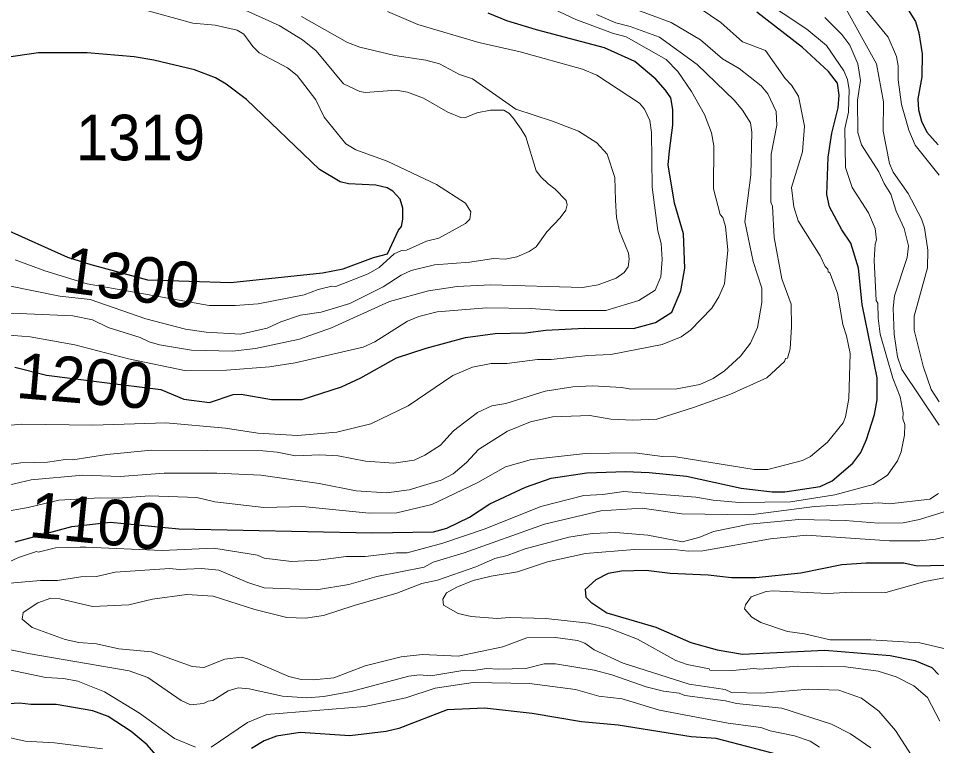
# Model space of a CAD drawing. Extents: x 598.3 to 623.2, y 6902.2 to 6930.1.
# Drawn here: x 611.511 to 613.12, y 6916.884 to 6918.158 of the extents above; entities that cross this region are included whole.
import ezdxf
from ezdxf.enums import TextEntityAlignment as Align

# ---------------------------------------------------------------- set-up
doc = ezdxf.new("R2010")
doc.units = 0
doc.header["$LTSCALE"] = 0.032
doc.layers.add('1', color=7, linetype='Continuous', lineweight=25)
doc.layers.add('2', color=7, linetype='Continuous', lineweight=13)
doc.layers.add('21', color=7, linetype='Continuous')
doc.layers.add('61', color=7, linetype='Continuous')

msp = doc.modelspace()

# ---------------------------------------------------------------- linework, layer by layer
at = {"layer": '1'}
for points in [[(613.057, 6918.194), (613.0824, 6918.1525), (613.0882, 6918.1326), (613.0943, 6918.0959), (613.0936, 6918.0553), (613.0864, 6918.0171), (613.088, 6917.9976), (613.0929, 6917.9779), (613.1024, 6917.9588), (613.1221, 6917.9365)], [(611.5054, 6917.2411), (611.6046, 6917.2681), (611.6723, 6917.2757), (611.7924, 6917.2638), (612.1301, 6917.2567), (612.2383, 6917.2584), (612.2614, 6917.265), (612.3015, 6917.2844), (612.3366, 6917.3076), (612.3996, 6917.3367), (612.4443, 6917.3524), (612.5065, 6917.3619), (612.5745, 6917.3643), (612.6161, 6917.3628), (612.6813, 6917.3563), (612.7772, 6917.335), (612.8315, 6917.3288), (612.8535, 6917.3288), (612.9157, 6917.3383), (612.9363, 6917.348), (612.9728, 6917.3787), (612.9868, 6917.3976), (612.9968, 6917.4202), (613.0109, 6917.464), (613.0152, 6917.4899), (613.0151, 6917.5281), (612.9893, 6917.6571), (612.9827, 6917.7205), (612.969, 6917.7642), (612.9532, 6917.7876), (612.9316, 6917.8276), (612.927, 6917.8497), (612.9294, 6917.9151), (612.9358, 6917.9569), (612.9472, 6918.0014), (612.9487, 6918.0235), (612.9461, 6918.0446), (612.9303, 6918.0651), (612.8843, 6918.1072), (612.8044, 6918.1691)], [(612.6269, 6917.6252), (612.6559, 6917.6432), (612.6713, 6917.6807), (612.6785, 6917.7207), (612.6759, 6917.7804), (612.6605, 6917.8341), (612.6493, 6917.9015), (612.6517, 6917.9259), (612.6573, 6917.9707), (612.6574, 6917.9984), (612.6541, 6918.0189), (612.6444, 6918.0323), (612.6275, 6918.0513), (612.5907, 6918.0825), (612.5378, 6918.1065), (612.4184, 6918.138), (612.3669, 6918.1539), (612.3342, 6918.1671)], [(611.4881, 6917.7889), (611.5972, 6917.7398), (611.638, 6917.7271), (611.7371, 6917.7), (611.8834, 6917.6954), (612.0437, 6917.7124), (612.0797, 6917.719), (612.1331, 6917.7392), (612.1577, 6917.7454), (612.177, 6917.7873), (612.1821, 6917.7936), (612.1846, 6917.806), (612.1843, 6917.8254), (612.1798, 6917.8416), (612.1667, 6917.8556), (612.1573, 6917.8612), (612.1372, 6917.8658), (612.0895, 6917.8681), (612.0748, 6917.8719), (612.0383, 6917.8934), (611.9104, 6918.0157), (611.8751, 6918.0428), (611.8562, 6918.0539), (611.8194, 6918.0676), (611.7484, 6918.0849), (611.7139, 6918.0906), (611.6316, 6918.0977), (611.5461, 6918.0977), (611.4282, 6918.0809)], [(611.5046, 6917.5472), (611.5603, 6917.5328), (611.6571, 6917.5208), (611.7604, 6917.5077), (611.8008, 6917.491), (611.846, 6917.4851), (611.8871, 6917.4992), (611.9011, 6917.4996), (611.9544, 6917.4907), (612.0084, 6917.4907), (612.0768, 6917.5127), (612.1107, 6917.5285), (612.1735, 6917.5635), (612.2254, 6917.5805), (612.2941, 6917.599), (612.3462, 6917.6063), (612.3996, 6917.6071), (612.4352, 6917.6121), (612.5028, 6917.6152), (612.5887, 6917.615), (612.6269, 6917.6252)], [(613.178, 6917.2007), (613.0855, 6917.1986), (613.0621, 6917.204), (612.9962, 6917.2039), (612.9533, 6917.2008), (612.8814, 6917.1864), (612.803, 6917.1781), (612.7602, 6917.1782), (612.7191, 6917.183), (612.6528, 6917.1854), (612.6107, 6917.1911), (612.5675, 6917.1896), (612.5443, 6917.1855), (612.5228, 6917.1747), (612.504, 6917.1576), (612.5052, 6917.1442), (612.5137, 6917.1352), (612.5418, 6917.1169), (612.6275, 6917.0918), (612.6887, 6917.0648), (612.735, 6917.0518), (612.7797, 6917.0446), (612.9235, 6917.0511), (613.0381, 6917.0421), (613.0812, 6917.0333), (613.1108, 6917.0208), (613.123, 6917.0088)], [(611.7555, 6916.864), (611.7367, 6916.8853), (611.7088, 6916.9091), (611.6681, 6916.9353), (611.6414, 6916.9448), (611.5773, 6916.9562), (611.5331, 6916.9564), (611.513, 6916.9587), (611.4017, 6916.9517), (611.3628, 6916.9562), (611.3382, 6916.9635), (611.2941, 6916.9893), (611.287, 6916.9974), (611.2811, 6917.0003), (611.2242, 6917.0836), (611.2056, 6917.1012), (611.1731, 6917.1036), (611.1639, 6917.102), (611.1511, 6917.0952), (611.1343, 6917.082), (611.1203, 6917.0627), (611.0932, 6917.0106), (611.0735, 6916.9867)], [(612.8406, 6916.8688), (612.7334, 6916.8964), (612.6898, 6916.8997), (612.5615, 6916.92), (612.4973, 6916.9256), (612.4109, 6916.9402), (612.3274, 6916.9498), (612.2623, 6916.9466), (612.1774, 6916.914), (612.1551, 6916.9086), (612.0914, 6916.9014), (612.0046, 6916.907), (611.9631, 6916.9006), (611.9417, 6916.8924), (611.9195, 6916.8793)]]:
    msp.add_lwpolyline(points, dxfattribs=at)
at = {"layer": '2'}
for points in [[(612.766, 6918.223), (612.8919, 6918.1392), (612.9263, 6918.1104), (612.9572, 6918.0662), (612.9633, 6918.0508), (612.9665, 6918.033), (612.9649, 6917.9939), (612.9585, 6917.965), (612.9601, 6917.8968), (612.9713, 6917.8618), (613.0004, 6917.8171), (613.0118, 6917.7901), (613.0144, 6917.77), (613.0119, 6917.7626), (613.0103, 6917.7345), (613.0135, 6917.6636), (613.0167, 6917.6592), (613.0168, 6917.6326), (613.0206, 6917.6049), (613.0427, 6917.5276), (613.0558, 6917.495), (613.0611, 6917.4669), (613.0605, 6917.4566), (613.0637, 6917.4469), (613.063, 6917.4281), (613.0574, 6917.3989), (613.0511, 6917.383), (613.0335, 6917.3578), (613.0084, 6917.3415), (612.9414, 6917.3236), (612.8635, 6917.311), (612.7737, 6917.3102), (612.7279, 6917.314), (612.6976, 6917.3191), (612.5715, 6917.3295), (612.5349, 6917.3239), (612.5017, 6917.3222), (612.4264, 6917.303), (612.3285, 6917.2638), (612.2545, 6917.2389), (612.1918, 6917.2217), (612.1733, 6917.2218), (612.1188, 6917.2154), (612.0853, 6917.2153), (612.0364, 6917.2088), (611.9894, 6917.2065)], [(612.509, 6918.2052), (612.6544, 6918.151), (612.7057, 6918.1205), (612.7445, 6918.0874), (612.7737, 6918.0704), (612.8122, 6918.0399), (612.8236, 6918.0259), (612.8386, 6917.9946), (612.8394, 6917.9711), (612.8298, 6917.9203), (612.829, 6917.8363), (612.8321, 6917.829), (612.8348, 6917.7744), (612.8483, 6917.702), (612.8645, 6917.6574), (612.8653, 6917.6179), (612.8628, 6917.579)], [(612.963, 6918.2131), (613.0345, 6918.1251), (613.0491, 6918.0912), (613.0523, 6918.0751), (613.0524, 6918.0503), (613.0577, 6918.0069), (613.0706, 6917.962), (613.0821, 6917.9358), (613.1238, 6917.8835)], [(611.8784, 6918.186), (611.9679, 6918.1453), (612.0087, 6918.1205), (612.0329, 6918.1013), (612.0803, 6918.0432), (612.1093, 6918.0301), (612.1191, 6918.0282), (612.1729, 6918.0322), (612.1925, 6918.029), (612.2205, 6918.0183), (612.2634, 6917.9935), (612.2859, 6917.9843), (612.2931, 6917.9837), (612.3144, 6917.9926), (612.3382, 6917.9973), (612.3612, 6917.9971), (612.3702, 6917.9922), (612.3773, 6917.9841), (612.392, 6917.9638), (612.4002, 6917.9507), (612.4178, 6917.8907)], [(612.9521, 6918.1905), (613.0144, 6918.0781), (613.0264, 6918.0119), (613.0256, 6917.9604), (613.0369, 6917.9037), (613.0436, 6917.8887), (613.0695, 6917.8514), (613.0927, 6917.8066), (613.0985, 6917.7909), (613.104, 6917.7522), (613.1034, 6917.7208)], [(611.4729, 6917.6047), (611.5316, 6917.6), (611.6102, 6917.5861), (611.7038, 6917.5618), (611.8052, 6917.5409), (611.8754, 6917.5417), (611.9508, 6917.5474), (611.9958, 6917.5546), (612.1151, 6917.5819), (612.1355, 6917.5915), (612.1927, 6917.6274), (612.2127, 6917.6357), (612.2448, 6917.6437), (612.3313, 6917.6509), (612.4086, 6917.65), (612.4589, 6917.6461), (612.5399, 6917.6464), (612.5977, 6917.664), (612.6265, 6917.6818), (612.6362, 6917.7054), (612.6387, 6917.7357), (612.6372, 6917.7637), (612.6314, 6917.7856), (612.621, 6917.8625), (612.6201, 6917.958), (612.6169, 6917.9793), (612.608, 6917.9992), (612.5988, 6918.0097), (612.5241, 6918.0587), (612.4994, 6918.0689), (612.39, 6918.0994), (612.3176, 6918.1155), (612.2105, 6918.147), (612.1576, 6918.17)], [(611.5057, 6917.7352), (611.5574, 6917.7158), (611.6315, 6917.6931), (611.8451, 6917.6548), (611.8908, 6917.655), (611.9313, 6917.6582), (612.0117, 6917.6736), (612.0362, 6917.6833), (612.0599, 6917.6889), (612.0669, 6917.6882), (612.124, 6917.7103), (612.1429, 6917.7215), (612.1692, 6917.7454), (612.1821, 6917.7513), (612.191, 6917.7521), (612.2262, 6917.768), (612.2475, 6917.773), (612.2941, 6917.7984), (612.302, 6917.8063), (612.3034, 6917.8193), (612.294, 6917.8344), (612.2432, 6917.8669), (612.1568, 6917.9081), (612.1023, 6917.9276), (612.0848, 6917.9384), (612.0468, 6917.9847), (612.0323, 6918.0155), (611.9996, 6918.0577), (611.9826, 6918.0713), (611.9331, 6918.0976), (611.9217, 6918.1089), (611.9057, 6918.1304), (611.8943, 6918.1374), (611.8559, 6918.1463), (611.8169, 6918.1496), (611.7275, 6918.1739)], [(612.4491, 6918.1744), (612.4876, 6918.1559), (612.5515, 6918.132), (612.5759, 6918.1256), (612.6458, 6918.0857), (612.6664, 6918.0651), (612.6904, 6918.03), (612.7129, 6917.9899), (612.7251, 6917.9575), (612.7293, 6917.9345), (612.7286, 6917.8597), (612.7403, 6917.8146), (612.7449, 6917.8091), (612.7496, 6917.7934), (612.7537, 6917.7517), (612.7481, 6917.6933), (612.7381, 6917.6701), (612.7257, 6917.6504), (612.6884, 6917.6116), (612.672, 6917.6001), (612.6389, 6917.5865)], [(612.8653, 6918.0411), (612.8544, 6918.0525), (612.82, 6918.1017), (612.7795, 6918.1169), (612.7413, 6918.1505), (612.7054, 6918.1753)], [(611.4557, 6917.3712), (611.5154, 6917.3797), (611.5619, 6917.3806), (611.5937, 6917.3853), (611.6063, 6917.3849), (611.6663, 6917.3942), (611.7442, 6917.4015), (611.9391, 6917.4007), (611.9642, 6917.3984), (611.9966, 6917.3919), (612.0393, 6917.3935), (612.0711, 6917.3919), (612.1193, 6917.3822), (612.169, 6917.379), (612.2043, 6917.384), (612.2232, 6917.3928), (612.2503, 6917.4106), (612.273, 6917.4357), (612.3155, 6917.4678), (612.3403, 6917.4793), (612.3651, 6917.4834), (612.4337, 6917.5051), (612.482, 6917.5124), (612.517, 6917.5142), (612.5683, 6917.5116), (612.5836, 6917.5085), (612.6647, 6917.5093), (612.7046, 6917.5166), (612.7281, 6917.527), (612.748, 6917.5408), (612.7759, 6917.5664), (612.7932, 6917.5891), (612.806, 6917.6164), (612.8135, 6917.6604), (612.8134, 6917.6855), (612.7981, 6917.7319), (612.7837, 6917.8022), (612.7941, 6917.8838), (612.7957, 6917.9588), (612.7932, 6917.975), (612.7795, 6917.9973), (612.7654, 6918.014), (612.7003, 6918.0774), (612.634, 6918.1251), (612.5824, 6918.144), (612.5577, 6918.1499), (612.5235, 6918.1647)], [(612.0597, 6917.6159), (612.1611, 6917.6618), (612.2294, 6917.6807), (612.2799, 6917.6881), (612.3388, 6917.6914), (612.4993, 6917.6866), (612.5265, 6917.6914), (612.5584, 6917.7027), (612.5719, 6917.7128), (612.579, 6917.7228), (612.5809, 6917.736), (612.5796, 6917.747), (612.5642, 6917.7853), (612.5586, 6917.809), (612.5569, 6917.8397), (612.5561, 6917.8792), (612.5422, 6917.9199), (612.5244, 6917.94), (612.492, 6917.9602), (612.4467, 6917.978), (612.3822, 6917.9989), (612.3063, 6918.0518), (612.2836, 6918.0597), (612.2488, 6918.0782), (612.2249, 6918.0848), (612.1703, 6918.0928), (612.1091, 6918.1076), (612.0874, 6918.1155), (612.0068, 6918.1615)], [(613.1242, 6917.4457), (613.0586, 6917.543), (613.0508, 6917.5649), (613.0449, 6917.6049), (613.0434, 6917.6503), (613.0458, 6917.6717), (613.0676, 6917.7394), (613.0701, 6917.7595), (613.0629, 6917.7899), (613.0486, 6917.8203), (613.0393, 6917.8503), (613.0277, 6917.8685), (613.0182, 6917.8892), (612.9881, 6917.9365), (612.9812, 6917.9583), (612.9811, 6918.0146), (612.9859, 6918.0492), (612.9812, 6918.0781), (612.9672, 6918.111), (612.9532, 6918.1298), (612.9234, 6918.1594)], [(611.4823, 6917.2932), (611.5282, 6917.3012), (611.5817, 6917.3141), (611.6541, 6917.3181), (611.686, 6917.3173), (611.7405, 6917.3214), (611.8236, 6917.319), (611.855, 6917.3112), (611.9412, 6917.3012), (612.0087, 6917.3028), (612.1257, 6917.2915), (612.1738, 6917.2918), (612.2354, 6917.3063), (612.3157, 6917.3449), (612.3643, 6917.3724), (612.4099, 6917.3854), (612.5045, 6917.3959), (612.5904, 6917.3967), (612.6393, 6917.3903), (612.6628, 6917.3902), (612.7997, 6917.3677), (612.8238, 6917.3676), (612.8846, 6917.3834), (612.8983, 6917.3908), (612.9283, 6917.4159), (612.9556, 6917.4496), (612.96, 6917.4598), (612.9657, 6917.492), (612.9682, 6917.571), (612.9619, 6917.6018), (612.9553, 6917.6215), (612.9456, 6917.6766), (612.9325, 6917.7123), (612.9294, 6917.7143), (612.9292, 6917.7189), (612.9244, 6917.7232), (612.9154, 6917.7418), (612.8768, 6917.8031), (612.8694, 6917.8277), (612.8654, 6917.8618), (612.8847, 6917.924), (612.888, 6917.9692), (612.8773, 6918.022), (612.8653, 6918.0411)], [(612.4178, 6917.8907), (612.4261, 6917.8804), (612.4389, 6917.8681), (612.4515, 6917.8591), (612.4708, 6917.839), (612.4725, 6917.8312), (612.4701, 6917.8222), (612.4602, 6917.8089), (612.4367, 6917.7841), (612.4179, 6917.758), (612.4057, 6917.7498), (612.3843, 6917.7401), (612.3639, 6917.7363), (612.3432, 6917.7375), (612.3019, 6917.7309), (612.2399, 6917.7262), (612.1992, 6917.7164), (612.1817, 6917.7084), (612.1501, 6917.6879), (612.0916, 6917.6585), (612.0412, 6917.6434), (612.0052, 6917.638), (611.9709, 6917.6266), (611.9469, 6917.6151), (611.8999, 6917.6048), (611.8401, 6917.6084), (611.8039, 6917.6137), (611.7346, 6917.6319), (611.6371, 6917.6654), (611.5838, 6917.6716), (611.4942, 6917.6895)], [(613.1034, 6917.7208), (613.0799, 6917.6366), (613.0803, 6917.6116), (613.0958, 6917.5487), (613.1101, 6917.5079), (613.1239, 6917.4862)], [(611.4487, 6917.6396), (611.5123, 6917.6412), (611.6064, 6917.6372), (611.6407, 6917.6298), (611.6684, 6917.6168), (611.7246, 6917.5991), (611.7402, 6917.5913), (611.7581, 6917.5859), (611.8142, 6917.5768), (611.886, 6917.5749), (611.9262, 6917.5797), (612.0036, 6917.5959), (612.0597, 6917.6159)], [(612.8628, 6917.579), (612.8582, 6917.5629), (612.8548, 6917.5623), (612.853, 6917.5569), (612.8223, 6917.5285), (612.7575, 6917.4994), (612.6935, 6917.4762), (612.6293, 6917.4561), (612.5875, 6917.4543), (612.5487, 6917.456), (612.5119, 6917.4622), (612.4466, 6917.4598), (612.4083, 6917.451), (612.368, 6917.435), (612.3168, 6917.4027), (612.2958, 6917.38), (612.2729, 6917.3601), (612.2518, 6917.3493), (612.1955, 6917.3322), (612.1561, 6917.3272), (612.103, 6917.3304), (612.0378, 6917.3434), (611.936, 6917.3578), (611.8587, 6917.3611), (611.7663, 6917.3611), (611.6892, 6917.3554), (611.6241, 6917.3578), (611.5335, 6917.3497), (611.3742, 6917.3125)], [(612.6389, 6917.5865), (612.5486, 6917.5691), (612.5084, 6917.5675), (612.4442, 6917.5603), (612.4204, 6917.5602), (612.3665, 6917.5533), (612.3394, 6917.5537), (612.3063, 6917.5473), (612.2718, 6917.5326), (612.1941, 6917.4791), (612.1285, 6917.448), (612.0691, 6917.4333), (612, 6917.4274), (611.9307, 6917.4315), (611.874, 6917.4404), (611.7696, 6917.4493), (611.6417, 6917.4453), (611.5164, 6917.447), (611.3967, 6917.4364)], [(611.4295, 6917.1628), (611.5499, 6917.1732), (611.5797, 6917.1733), (611.6206, 6917.1797), (611.6479, 6917.1806), (611.6809, 6917.1878), (611.7766, 6917.1944), (611.7926, 6917.1928), (611.8319, 6917.1943), (611.8622, 6917.1912), (611.9129, 6917.1699), (611.9418, 6917.1604), (612.033, 6917.1572), (612.0898, 6917.1666), (612.1388, 6917.1804), (612.2218, 6917.1967), (612.2375, 6917.2056), (612.292, 6917.222), (612.4326, 6917.2721), (612.5316, 6917.2956), (612.6039, 6917.3003), (612.6729, 6917.2899), (612.7936, 6917.2883), (612.9053, 6917.3029), (613.0185, 6917.3093), (613.0368, 6917.3077), (613.1075, 6917.3161), (613.123, 6917.326)], [(613.1514, 6917.2994), (613.0896, 6917.2801), (613.0611, 6917.2745), (613.0178, 6917.2737), (612.9592, 6917.2786), (612.878, 6917.2801), (612.7915, 6917.272), (612.7286, 6917.2591), (612.7049, 6917.249), (612.6741, 6917.2413), (612.6136, 6917.2526), (612.5573, 6917.2574), (612.5163, 6917.2558), (612.4755, 6917.2495), (612.3989, 6917.2291), (612.367, 6917.2169), (612.3459, 6917.2119), (612.3123, 6917.1974), (612.2455, 6917.1741), (612.2176, 6917.1681), (612.1739, 6917.1509), (612.0991, 6917.1296), (612.0457, 6917.1118), (612.014, 6917.1072), (611.9816, 6917.1083), (611.9254, 6917.1228), (611.8525, 6917.1458), (611.8062, 6917.1491), (611.7458, 6917.1409), (611.7044, 6917.1305), (611.6407, 6917.128), (611.5837, 6917.141), (611.5678, 6917.1425), (611.545, 6917.1343), (611.5195, 6917.1175), (611.5176, 6917.1056), (611.5355, 6917.0911), (611.5928, 6917.0703), (611.6169, 6917.065), (611.6482, 6917.0624), (611.6871, 6917.0535), (611.7442, 6917.0486), (611.8153, 6917.0228), (611.8362, 6917.0212), (611.8727, 6917.0358), (611.9016, 6917.0389), (611.9132, 6917.0362), (611.9849, 6917.0051), (612.0064, 6917.0002), (612.0283, 6916.9993), (612.0638, 6917.0027), (612.1188, 6917.024), (612.1813, 6917.0397), (612.219, 6917.0438), (612.2817, 6917.0406), (612.3599, 6917.0572), (612.4015, 6917.0729), (612.452, 6917.0737), (612.4904, 6917.0681), (612.5033, 6917.0637), (612.5196, 6917.052), (612.5702, 6917.0283), (612.6863, 6916.992), (612.749, 6916.9823), (612.7603, 6916.9773), (612.8133, 6916.9758), (612.8958, 6916.983), (612.9482, 6916.9815), (612.9879, 6916.9675), (613.018, 6916.9446), (613.0476, 6916.9104), (613.0854, 6916.8519)], [(613.1606, 6917.2558), (613.1178, 6917.246), (613.0902, 6917.243), (613.0368, 6917.2429), (612.8915, 6917.2526), (612.8287, 6917.2461), (612.7097, 6917.2252), (612.6844, 6917.2245), (612.6544, 6917.2283), (612.5903, 6917.2276), (612.5046, 6917.2204), (612.4377, 6917.2058), (612.3856, 6917.1887), (612.3395, 6917.1812), (612.3076, 6917.1732), (612.2793, 6917.1619), (612.2609, 6917.1515), (612.2543, 6917.1406), (612.2555, 6917.13), (612.2817, 6917.1157), (612.3043, 6917.1103), (612.3496, 6917.107), (612.3711, 6917.1085), (612.435, 6917.1069), (612.5098, 6917.0989), (612.5442, 6917.0904), (612.5953, 6917.0708), (612.6628, 6917.033), (612.6826, 6917.0265), (612.7208, 6917.0187), (612.7224, 6917.0163), (612.7619, 6917.0155), (612.7993, 6917.0193)], [(611.9894, 6917.2065), (611.9416, 6917.2126), (611.9301, 6917.2178), (611.8533, 6917.2299), (611.7628, 6917.226), (611.6291, 6917.2316), (611.6196, 6917.2318), (611.576, 6917.2306), (611.5459, 6917.2231), (611.5427, 6917.2242), (611.5111, 6917.2137), (611.4638, 6917.1912)], [(613.1455, 6917.1801), (613.0988, 6917.1715), (613.0307, 6917.1525), (612.9703, 6917.153), (612.9286, 6917.1507), (612.8333, 6917.1554), (612.8211, 6917.1539), (612.7948, 6917.1447), (612.7846, 6917.1306), (612.783, 6917.124), (612.7958, 6917.1094), (612.8115, 6917.1), (612.8581, 6917.0842), (612.8878, 6917.0801), (612.9329, 6917.0697), (613.0044, 6917.0697), (613.0901, 6917.0642), (613.1375, 6917.0531)], [(611.532, 6917.045), (611.4117, 6917.0694)], [(613.0044, 6916.8804), (612.9688, 6916.9047), (612.9353, 6916.9218), (612.8482, 6916.9499), (612.769, 6916.9579), (612.7496, 6916.9628), (612.6787, 6916.9717), (612.6685, 6916.9758), (612.641, 6916.9795), (612.611, 6916.987), (612.5503, 6917.0082), (612.5195, 6917.0163), (612.452, 6917.0275), (612.4321, 6917.0275), (612.4002, 6917.0195), (612.3519, 6917.0179), (612.3317, 6917.0194), (612.3082, 6917.0158), (612.2931, 6917.0162), (612.2335, 6917.0066), (612.2137, 6917.0081), (612.1949, 6917.0058), (612.0942, 6916.9791), (612.046, 6916.9702), (612.0165, 6916.9677), (611.9736, 6916.971), (611.9156, 6916.9839), (611.8962, 6916.9854), (611.8787, 6916.9799), (611.8516, 6916.9629), (611.8436, 6916.9622), (611.8356, 6916.9577), (611.8123, 6916.9556), (611.7964, 6916.9629), (611.738, 6917.0032), (611.7051, 6917.0153), (611.532, 6917.045)], [(611.4777, 6917.0202), (611.5589, 6917.0032), (611.5902, 6917.0017), (611.615, 6916.9968), (611.662, 6916.9781), (611.723, 6916.9411), (611.7845, 6916.8966), (611.8212, 6916.8816)], [(612.7993, 6917.0193), (612.8101, 6917.0179), (612.8764, 6917.0235), (612.9607, 6917.0219), (613.0173, 6917.0145), (613.0486, 6917.0044), (613.0798, 6916.9887), (613.1037, 6916.9682), (613.1252, 6916.9272)], [(611.6584, 6916.8786), (611.5745, 6916.8891), (611.523, 6916.8917), (611.4677, 6916.9045), (611.4348, 6916.9176), (611.3393, 6916.9192), (611.305, 6916.9299), (611.274, 6916.9494), (611.2353, 6916.9853), (611.2113, 6917.0033), (611.1776, 6917.0025)], [(611.8486, 6916.8812), (611.9124, 6916.9246), (611.9461, 6916.9384), (612.1182, 6916.9528), (612.1897, 6916.9677), (612.2412, 6916.9846), (612.3079, 6916.9945), (612.4064, 6916.9927), (612.4871, 6916.9823), (612.5276, 6916.971), (612.5686, 6916.966), (612.6339, 6916.9464), (612.7543, 6916.9236), (612.8117, 6916.9157), (612.8282, 6916.91), (612.8708, 6916.9014), (612.8978, 6916.8919), (612.9143, 6916.8814)]]:
    msp.add_lwpolyline(points, dxfattribs=at)

# ---------------------------------------------------------------- texts
at = {"layer": '21', "width": 0.95}
msp.add_text('1319', height=0.08, dxfattribs=at).set_placement((611.6119, 6917.9093))
at = {"layer": '61'}
for s, rotation, p in [('1300', 352.569, (611.7042, 6917.664)), ('1200', 355.156, (611.6241, 6917.4834)), ('1100', 354.289, (611.6462, 6917.238))]:
    msp.add_text(s, height=0.08, rotation=rotation, dxfattribs=at).set_placement(p, align=Align.CENTER)

doc.saveas('drawing.dxf')
